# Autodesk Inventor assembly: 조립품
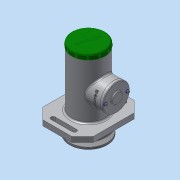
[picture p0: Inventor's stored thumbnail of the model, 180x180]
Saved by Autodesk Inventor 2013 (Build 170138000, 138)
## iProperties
Created: 2017-10
Part Number: 조립품
Document SubType Name: Assembly
Designer: dgall
Author: dgall
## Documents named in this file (20)
- C:\Users\dgall\Desktop\471007V1025\조립품.iam
- C:\Users\dgall\Desktop\471007V1025\본체.ipt
- C:\Users\dgall\Desktop\471007V1025\베어링 15 x 35 x 11.ipt
- C:\Users\dgall\Desktop\471007V1025\부시1.ipt
- C:\Users\dgall\Desktop\471007V1025\축.ipt
- C:\Users\dgall\Desktop\471007V1025\키 4 x 4 x 18.ipt
- C:\Users\dgall\Desktop\471007V1025\오일 실 15 25 7.ipt
- C:\Users\dgall\Desktop\471007V1025\멈춤링 15 x 1.ipt
- C:\Users\dgall\Desktop\471007V1025\멈춤링 35x1.6.ipt
- C:\Users\dgall\Desktop\471007V1025\부시2.ipt
- C:\Users\dgall\Desktop\471007V1025\와셔 10x21.ipt
- C:\Users\dgall\Desktop\471007V1025\너트 M10.ipt
- C:\Users\dgall\Desktop\471007V1025\사이드 커버.ipt
- 사이드 커버.ipt
- C:\Users\dgall\Desktop\471007V1025\탑 커버.ipt
- C:\Users\dgall\Desktop\471007V1025\십자볼트 M3 x 10.ipt
- C:\Users\dgall\Desktop\471007V1025\와셔 3x6.ipt
- C:\Users\dgall\Desktop\471007V1025\V-벨트풀리.ipt
- C:\Users\dgall\Desktop\471007V1025\볼트 M4 x 10.ipt
- C:\Users\dgall\Desktop\471007V1025\와셔 4x16.ipt
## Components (2 placed, 2 different names)
1. V-벨트풀리:1
2. ISO 4017 M4 x 10:1
